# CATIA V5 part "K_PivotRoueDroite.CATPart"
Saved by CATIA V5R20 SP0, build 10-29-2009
Part number: pivot_roue_droite
Publications: "Corps principal", "largeur pivot", "largeur de la glissière", "Longueur de barres du corps", "Point.1", "Point.2", "Droite.1", "Droite.3"
Bounding box of the stored display mesh (mm): x -20 to 20, y -625 to -500, z 0 to 0
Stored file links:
  G:\Khaled_CFAO_2011\ST2M\ST2M_GR1\cdurantin\cdurantin\Khaled\CAD_ThinkMOTION\K_PivotRoueDroite.CATPart
  G:\Khaled_CFAO_2011\ST2M\ST2M_GR1\cdurantin\cdurantin\Khaled\CAD_ThinkMOTION\K_PivotRoueGauche.CATPart
  G:\Khaled_CFAO_2011\ST2M\ST2M_GR1\cdurantin\cdurantin\Khaled\CAD_ThinkMOTION\K_Part4.CATPart
  G:\Khaled_CFAO_2011\ST2M\ST2M_GR1\cdurantin\cdurantin\Khaled\CAD_ThinkMOTION\K_Corps.CATPart
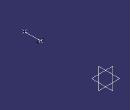
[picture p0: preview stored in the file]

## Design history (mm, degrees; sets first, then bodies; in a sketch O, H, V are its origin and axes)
External parameters (linked from other documents)
  `External.largeur pivot` = 125 mm
  `External.largeur de la glissière` = 100 mm
  `External.Longueur de barres du corps` = 800 mm
Body1 (main body)
  Point1: type OnPlane, Support xy-plane, H 0, V -625 {= -`External.largeur pivot` -`External.largeur de la glissière` -`External.Longueur de barres du corps` /2}, Direction (1, 0, 0)
  Point2: type OnPlane, Support xy-plane, H 0, V -500 {= -`External.largeur de la glissière` -`External.Longueur de barres du corps` /2}, Direction (1, 0, 0)
  Line1: type PtPt, FirstPoint Point2, SecondPoint Point1
  Line2: type Normal, RefPoint Point2, RefSkin yz-plane, Start -20, End 20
